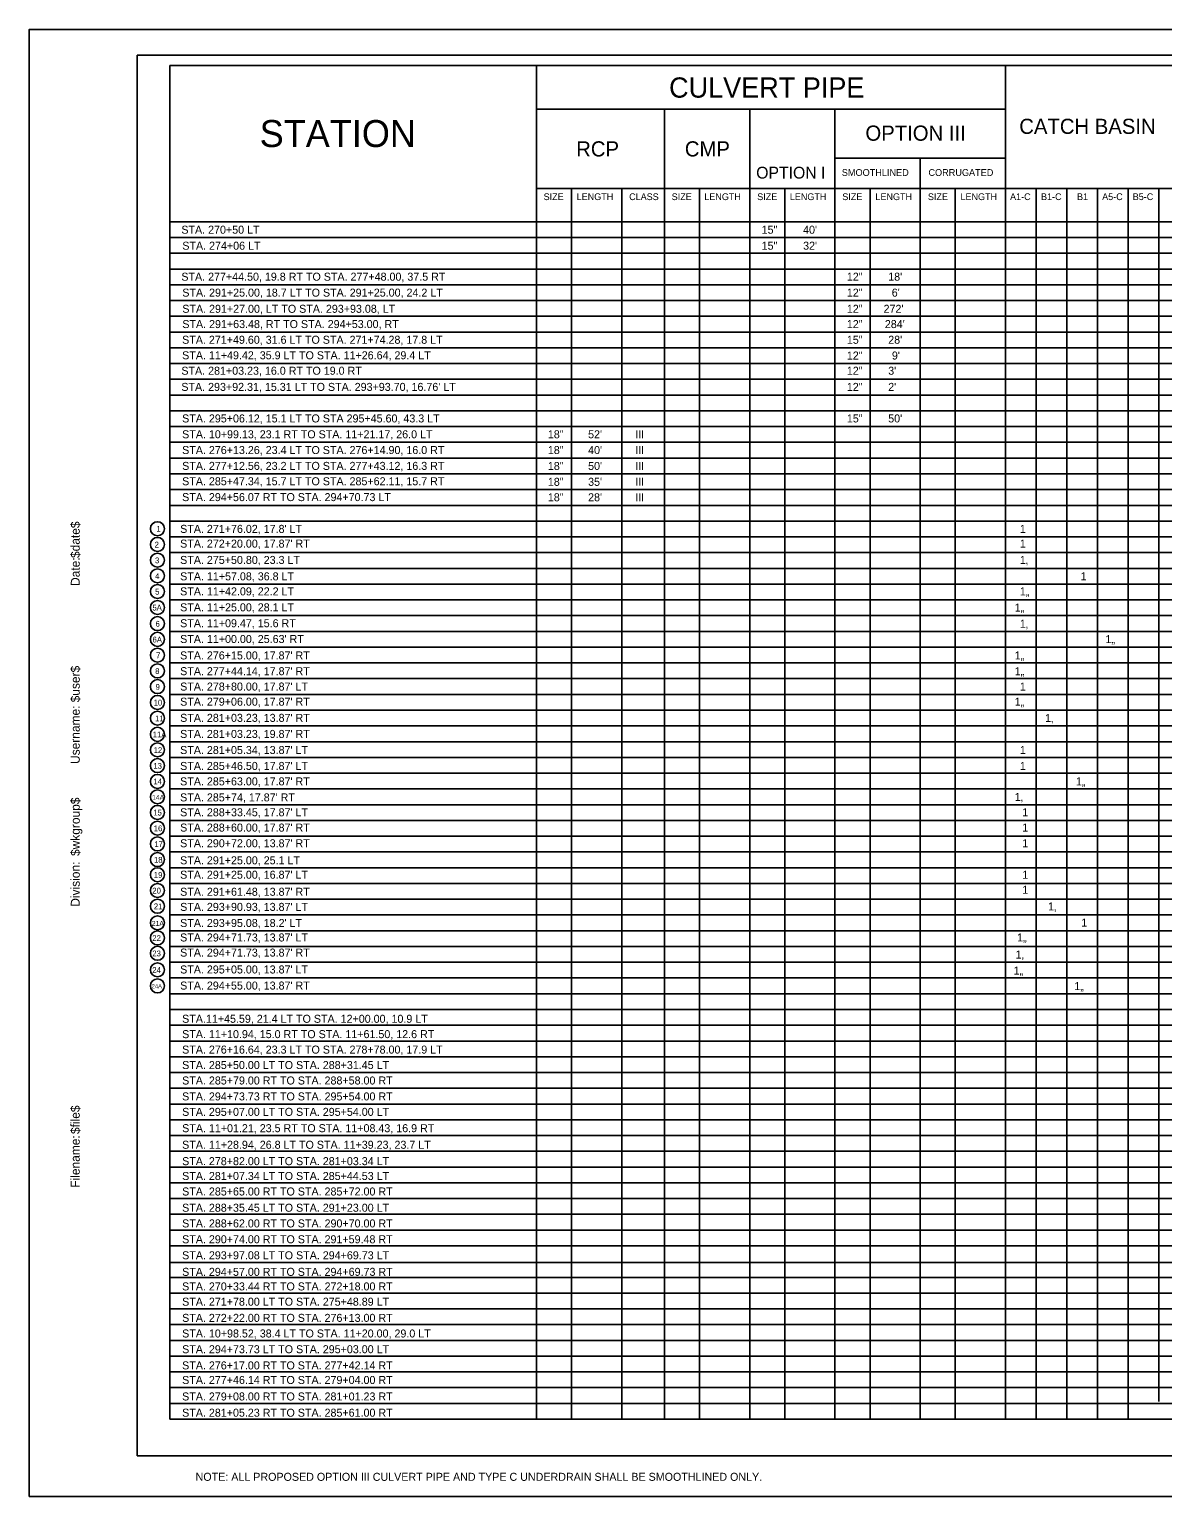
# Model space of a CAD drawing. Extents: x -0.13 to 2.7, y -0.05 to 1.78.
# Drawn here: x -0.135 to 1.282, y -0.051 to 1.782 of the extents above; entities that cross this region are included whole.
import ezdxf

# ---------------------------------------------------------------- set-up
doc = ezdxf.new("R2010")
doc.units = 0
for name, color, linetype in [('ANNOTATION', 7, 'Continuous'), ('BORDER', 7, 'Continuous'), ('PLOT BOUNDARY', 7, 'Continuous')]:
    doc.layers.add(name, color=color, linetype=linetype)

msp = doc.modelspace()

# ---------------------------------------------------------------- linework, layer by layer
at = {"layer": 'ANNOTATION'}
for centre in [(0.0252, 1.1584), (0.0252, 1.1388), (0.0252, 1.1191), (0.0252, 1.0995), (0.0252, 1.08), (0.0252, 1.06), (0.0252, 1.0398), (0.0252, 1.0202), (0.0252, 1.0004), (0.0252, 0.9807), (0.0252, 0.9611), (0.0252, 0.9414), (0.0252, 0.9217), (0.0252, 0.9015), (0.0252, 0.8821), (0.0252, 0.8624), (0.0252, 0.8427), (0.0252, 0.8234), (0.0252, 0.8039), (0.0252, 0.7842), (0.0252, 0.7646), (0.0252, 0.745), (0.0252, 0.7261), (0.0252, 0.7064), (0.0252, 0.6867), (0.0252, 0.666), (0.0252, 0.6471), (0.0252, 0.6279), (0.0252, 0.6073), (0.0252, 0.5872)]:
    msp.add_circle(centre, 0.00875, dxfattribs=at)
at = {"layer": 'BORDER'}
for p, q in [((2.6667, 1.75), (0, 1.75)), ((0, 1.75), (0, 0)), ((0.0408, 1.7373), (2.4546, 1.7373)), ((0.0408, 1.7373), (0.0408, 0.0459)), ((0.4991, 1.6825), (0.4991, 1.7373)), ((1.0852, 1.6825), (1.0852, 1.7373)), ((0.4991, 1.6214), (0.4991, 1.6825)), ((0.4991, 1.6825), (0.5429, 1.6825)), ((0.5429, 1.6825), (0.6056, 1.6825)), ((0.6056, 1.6825), (0.6589, 1.6825)), ((0.6589, 1.6214), (0.6589, 1.6825)), ((0.6589, 1.6825), (0.7028, 1.6825)), ((0.7028, 1.6825), (0.7655, 1.6825)), ((0.7655, 1.6214), (0.7655, 1.6825)), ((0.7655, 1.6825), (0.8093, 1.6825)), ((0.8093, 1.6825), (0.9159, 1.6825)), ((0.872, 1.5836), (0.872, 1.6825)), ((0.9159, 1.6825), (1.0852, 1.6825)), ((1.0852, 1.6214), (1.0852, 1.6825)), ((0.4991, 1.5836), (0.4991, 1.6214)), ((0.6589, 1.5836), (0.6589, 1.6214)), ((0.7655, 1.5836), (0.7655, 1.6214)), ((0.872, 1.6214), (0.9159, 1.6214)), ((0.9159, 1.6214), (1.0224, 1.6214)), ((0.9786, 1.5616), (0.9786, 1.6214)), ((1.0224, 1.6214), (1.0852, 1.6214)), ((1.0852, 1.5836), (1.0852, 1.6214)), ((1.0852, 1.5836), (1.0852, 1.6056)), ((0.4991, 1.5616), (0.4991, 1.5836)), ((0.4991, 1.5836), (0.5429, 1.5836)), ((0.5429, 1.5616), (0.5429, 1.5836)), ((0.5429, 1.5836), (0.6056, 1.5836)), ((0.6056, 1.5616), (0.6056, 1.5836)), ((0.6056, 1.5836), (0.6589, 1.5836)), ((0.6589, 1.5616), (0.6589, 1.5836)), ((0.6589, 1.5836), (0.7028, 1.5836)), ((0.7028, 1.5616), (0.7028, 1.5836)), ((0.7028, 1.5836), (0.7655, 1.5836)), ((0.7655, 1.5616), (0.7655, 1.5836)), ((0.7655, 1.5836), (0.8093, 1.5836)), ((0.8093, 1.5616), (0.8093, 1.5836)), ((0.8093, 1.5836), (0.872, 1.5836)), ((0.872, 1.5616), (0.872, 1.5836)), ((0.872, 1.5836), (0.9159, 1.5836)), ((0.9159, 1.5616), (0.9159, 1.5836)), ((0.9159, 1.5836), (0.9786, 1.5836)), ((0.9786, 1.5836), (1.0224, 1.5836)), ((1.0224, 1.5616), (1.0224, 1.5836)), ((1.0224, 1.5836), (1.0852, 1.5836)), ((1.0852, 1.5616), (1.0852, 1.5836)), ((1.0852, 1.5836), (1.1236, 1.5836)), ((1.1236, 1.5836), (1.1619, 1.5836)), ((1.1236, 1.5836), (1.1236, 0.0459)), ((1.1619, 1.5836), (1.2003, 1.5836)), ((1.1619, 1.5836), (1.1619, 0.0459)), ((1.2003, 1.5836), (1.2386, 1.5836)), ((1.2003, 1.5836), (1.2003, 0.0459)), ((1.2386, 1.5836), (1.277, 1.5836)), ((1.2386, 1.5836), (1.2386, 0.0459)), ((1.2669, 1.5836), (1.3734, 1.5836)), ((1.277, 1.5836), (1.277, 0.0679)), ((0.4991, 1.5616), (0.4991, 0.0459)), ((0.5429, 1.5616), (0.5429, 0.0459)), ((0.6056, 1.5616), (0.6056, 0.0459)), ((0.6589, 1.5616), (0.6589, 0.0459)), ((0.7028, 1.5616), (0.7028, 0.0459)), ((0.7655, 1.5616), (0.7655, 0.0459)), ((0.8093, 1.5616), (0.8093, 0.0459)), ((0.872, 1.5616), (0.872, 0.0459)), ((0.9159, 1.5616), (0.9159, 0.0459)), ((0.9786, 1.5616), (0.9786, 0.0459)), ((1.0224, 1.5616), (1.0224, 0.0459)), ((1.0852, 1.5616), (1.0852, 0.0459)), ((0.0408, 1.5419), (2.4546, 1.5419)), ((0.0408, 1.5223), (2.4546, 1.5223)), ((0.0408, 1.5026), (2.4546, 1.5026)), ((0.0408, 1.4829), (2.4546, 1.4829)), ((0.0408, 1.4632), (2.4546, 1.4632)), ((0.0408, 1.4435), (2.4546, 1.4435)), ((0.0408, 1.4238), (2.4546, 1.4238)), ((0.0408, 1.4041), (2.4546, 1.4041)), ((0.0408, 1.3845), (2.4546, 1.3845)), ((0.0408, 1.3648), (2.4546, 1.3648)), ((0.0408, 1.3451), (2.4546, 1.3451)), ((0.0408, 1.3254), (2.4546, 1.3254)), ((0.0408, 1.3057), (2.4546, 1.3057)), ((0.0408, 1.3057), (2.4546, 1.3057)), ((0.0408, 1.286), (2.4546, 1.286)), ((0.0408, 1.286), (2.4546, 1.286)), ((0.0408, 1.2664), (2.4546, 1.2664)), ((0.0408, 1.2664), (2.4546, 1.2664)), ((0.0408, 1.2467), (2.4546, 1.2467)), ((0.0408, 1.2467), (2.4546, 1.2467)), ((0.0408, 1.227), (2.4546, 1.227)), ((0.0408, 1.2073), (2.4546, 1.2073)), ((0.0408, 1.1876), (2.4546, 1.1876)), ((0.0408, 1.1679), (2.4546, 1.1679)), ((0.0408, 1.1482), (2.4546, 1.1482)), ((0.0408, 1.1286), (2.4546, 1.1286)), ((0.0408, 1.1089), (2.4546, 1.1089)), ((0.0408, 1.0892), (2.4546, 1.0892)), ((0.0408, 1.0695), (2.4546, 1.0695)), ((0.0408, 1.0498), (2.4546, 1.0498)), ((0.0408, 1.0301), (2.4546, 1.0301)), ((0.0408, 1.0104), (2.4546, 1.0104)), ((0.0408, 1.0104), (2.4546, 1.0104)), ((0.0408, 0.9908), (2.4546, 0.9908)), ((0.0408, 0.9711), (2.4546, 0.9711)), ((0.0408, 0.9514), (2.4546, 0.9514)), ((0.0408, 0.9317), (2.4546, 0.9317)), ((0.0408, 0.912), (2.4546, 0.912)), ((0.0408, 0.8923), (2.4546, 0.8923)), ((0.0408, 0.8727), (2.4546, 0.8727)), ((0.0408, 0.853), (2.4546, 0.853)), ((0.0408, 0.8333), (2.4546, 0.8333)), ((0.0408, 0.8136), (2.4546, 0.8136)), ((0.0408, 0.7939), (2.4546, 0.7939)), ((0.0408, 0.7742), (2.4546, 0.7742)), ((0.0408, 0.7545), (2.4546, 0.7545)), ((0.0408, 0.7349), (2.4546, 0.7349)), ((0.0408, 0.7152), (2.4546, 0.7152)), ((0.0408, 0.6955), (2.4546, 0.6955)), ((0.0408, 0.6758), (2.4546, 0.6758)), ((0.0408, 0.6561), (2.4546, 0.6561)), ((0.0408, 0.6364), (2.4546, 0.6364)), ((0.0408, 0.6167), (2.4546, 0.6167)), ((0.0408, 0.5971), (2.4546, 0.5971)), ((0.0408, 0.5774), (2.4546, 0.5774)), ((0.0408, 0.5577), (2.4546, 0.5577)), ((0.0408, 0.538), (2.4546, 0.538)), ((0.0408, 0.5183), (2.4546, 0.5183)), ((0.0408, 0.4986), (2.4546, 0.4986)), ((0.0408, 0.479), (2.4546, 0.479)), ((0.0408, 0.4593), (2.4546, 0.4593)), ((0.0408, 0.4396), (2.4546, 0.4396)), ((0.0408, 0.4199), (2.4546, 0.4199)), ((0.0408, 0.4002), (2.4546, 0.4002)), ((0.0408, 0.3805), (2.4546, 0.3805)), ((0.0408, 0.3608), (2.4546, 0.3608)), ((0.0408, 0.3412), (2.4546, 0.3412)), ((0.0408, 0.3215), (2.4546, 0.3215)), ((0.0408, 0.3018), (2.4546, 0.3018)), ((0.0408, 0.3018), (2.4546, 0.3018)), ((0.0408, 0.2821), (2.4546, 0.2821)), ((0.0408, 0.2624), (2.4546, 0.2624)), ((0.0408, 0.2417), (2.4546, 0.2417)), ((0.0408, 0.223), (2.4546, 0.223)), ((0.0408, 0.2034), (2.4546, 0.2034)), ((0.0408, 0.1837), (2.4546, 0.1837)), ((0.0408, 0.164), (2.4546, 0.164)), ((0.0408, 0.1443), (2.4546, 0.1443)), ((0.0408, 0.1246), (2.4546, 0.1246)), ((0.0408, 0.1049), (2.4546, 0.1049)), ((0.0408, 0.0853), (2.4546, 0.0853)), ((0.0408, 0.0656), (2.4546, 0.0656)), ((0.0408, 0.0459), (2.4546, 0.0459)), ((0, 0), (2.6667, 0))]:
    msp.add_line(p, q, dxfattribs=at)
at = {"layer": 'PLOT BOUNDARY'}
msp.add_lwpolyline([(-0.1349, -0.051), (2.6984, -0.051), (2.6984, 1.7823), (-0.1349, 1.7823)], close=True, dxfattribs=at)

# ---------------------------------------------------------------- texts
at = {"layer": 'ANNOTATION'}
for s, height, p in [('STA. 270+50 LT', 0.01, (0.0551, 1.527)), ('15"', 0.01, (0.7804, 1.527)), ("40'", 0.01, (0.8322, 1.527)), ('STA. 274+06 LT', 0.01, (0.0563, 1.507)), ('15"', 0.01, (0.7804, 1.507)), ("32'", 0.01, (0.8322, 1.507)), ('STA. 277+44.50, 19.8 RT TO STA. 277+48.00, 37.5 RT', 0.01, (0.0551, 1.4683)), ('12"', 0.01, (0.8869, 1.4683)), ("18'", 0.01, (0.9386, 1.4683)), ('STA. 291+25.00, 18.7 LT TO STA. 291+25.00, 24.2 LT', 0.01, (0.0563, 1.4484)), ('12"', 0.01, (0.8869, 1.4484)), ("6'", 0.01, (0.943, 1.4484)), ('STA. 291+27.00, LT TO STA. 293+93.08, LT', 0.01, (0.0563, 1.4282)), ('12"', 0.01, (0.8869, 1.4282)), ("272'", 0.01, (0.9328, 1.4282)), ('STA. 291+63.48, RT TO STA. 294+53.00, RT', 0.01, (0.0563, 1.4091)), ('12"', 0.01, (0.8869, 1.4091)), ("284'", 0.01, (0.9344, 1.4091)), ('STA. 271+49.60, 31.6 LT TO STA. 271+74.28, 17.8 LT', 0.01, (0.0561, 1.3895)), ('15"', 0.01, (0.8869, 1.3895)), ("28'", 0.01, (0.9386, 1.3895)), ('STA. 11+49.42, 35.9 LT TO STA. 11+26.64, 29.4 LT', 0.01, (0.0561, 1.3701)), ('12"', 0.01, (0.8869, 1.3698)), ("9'", 0.01, (0.9432, 1.3698)), ('STA. 281+03.23, 16.0 RT TO 19.0 RT', 0.01, (0.0551, 1.3508)), ('12"', 0.01, (0.8869, 1.3508)), ("3'", 0.01, (0.9386, 1.3508)), ("STA. 293+92.31, 15.31 LT TO STA. 293+93.70, 16.76' LT ", 0.01, (0.0551, 1.3306)), ('12"', 0.01, (0.8869, 1.3306)), ("2'", 0.01, (0.9386, 1.3306)), ('STA. 295+06.12, 15.1 LT TO STA 295+45.60, 43.3 LT', 0.01, (0.0561, 1.2912)), ('15"', 0.01, (0.8869, 1.2912)), ("50'", 0.01, (0.9386, 1.2912)), ('STA. 10+99.13, 23.1 RT TO STA. 11+21.17, 26.0 LT', 0.01, (0.0561, 1.2714)), ('18"', 0.01, (0.5132, 1.2714)), ("52'", 0.01, (0.5635, 1.2714)), ('III', 0.01, (0.6224, 1.2714)), ('STA. 276+13.26, 23.4 LT TO STA. 276+14.90, 16.0 RT', 0.01, (0.0561, 1.2517)), ('18"', 0.01, (0.5132, 1.2517)), ("40'", 0.01, (0.5635, 1.2517)), ('III', 0.01, (0.6224, 1.2517)), ('STA. 277+12.56, 23.2 LT TO STA. 277+43.12, 16.3 RT', 0.01, (0.0561, 1.2319)), ('18"', 0.01, (0.5132, 1.2318)), ("50'", 0.01, (0.5635, 1.2318)), ('III', 0.01, (0.6224, 1.2318)), ('STA. 285+47.34, 15.7 LT TO STA. 285+62.11, 15.7 RT', 0.01, (0.0561, 1.2127)), ('18"', 0.01, (0.5132, 1.212)), ("35'", 0.01, (0.5635, 1.212)), ('III', 0.01, (0.6224, 1.212)), ('STA. 294+56.07 RT TO STA. 294+70.73 LT', 0.01, (0.0561, 1.1929)), ('18"', 0.01, (0.5132, 1.1927)), ("28'", 0.01, (0.5635, 1.1927)), ('III', 0.01, (0.6224, 1.1927)), ('1', 0.00722, (0.024, 1.1546)), ("STA. 271+76.02, 17.8' LT", 0.01, (0.0536, 1.1532)), ('1', 0.01, (1.1031, 1.1532)), ('2', 0.00722, (0.0217, 1.1349)), ("STA. 272+20.00, 17.87' RT", 0.01, (0.0536, 1.1348)), ('1', 0.01, (1.1031, 1.1348)), ('3', 0.00722, (0.0222, 1.1152)), ('STA. 275+50.80, 23.3 LT', 0.01, (0.0536, 1.1144)), ('1‚', 0.01, (1.1031, 1.1144)), ('4', 0.00722, (0.0223, 1.0956)), ('STA. 11+57.08, 36.8 LT', 0.01, (0.0536, 1.0939)), ('1', 0.01, (1.179, 1.0939)), ('5', 0.00722, (0.0223, 1.0761)), ('STA. 11+42.09, 22.2 LT', 0.01, (0.0536, 1.0751)), ('1„', 0.01, (1.1031, 1.0751)), ('5A', 0.00722, (0.0189, 1.0562)), ('STA. 11+25.00, 28.1 LT ', 0.01, (0.0536, 1.0552)), ('1„', 0.01, (1.0967, 1.0549)), ('STA. 11+09.47, 15.6 RT', 0.01, (0.0536, 1.0353)), ('6', 0.00722, (0.0228, 1.036)), ('1‚', 0.01, (1.1031, 1.0347)), ('6A', 0.00722, (0.0191, 1.0163)), ("STA. 11+00.00, 25.63' RT", 0.01, (0.0536, 1.0156)), ('1„', 0.01, (1.2101, 1.0155)), ('7', 0.00722, (0.0235, 0.9966)), ("STA. 276+15.00, 17.87' RT", 0.01, (0.0536, 0.9951)), ('1„', 0.01, (1.0967, 0.9951)), ('8', 0.00722, (0.0224, 0.9769)), ("STA. 277+44.14, 17.87' RT", 0.01, (0.0536, 0.9754)), ('1„', 0.01, (1.0967, 0.9754)), ('9', 0.00722, (0.0229, 0.9572)), ("STA. 278+80.00, 17.87' LT", 0.01, (0.0536, 0.9562)), ('1', 0.01, (1.1031, 0.9562)), ('10', 0.00722, (0.0204, 0.9375)), ("STA. 279+06.00, 17.87' RT", 0.01, (0.0536, 0.9373)), ('1„', 0.01, (1.0967, 0.9373)), ('11', 0.00722, (0.0224, 0.9178)), ("STA. 281+03.23, 13.87' RT", 0.01, (0.0536, 0.9171)), ('1‚', 0.01, (1.1347, 0.9169)), ('11A', 0.00722, (0.0193, 0.8976)), ("STA. 281+03.23, 19.87' RT", 0.01, (0.0536, 0.897)), ('12', 0.00722, (0.0204, 0.8782)), ("STA. 281+05.34, 13.87' LT", 0.01, (0.0536, 0.8769)), ('1', 0.01, (1.1031, 0.8769)), ('13', 0.00722, (0.0201, 0.8585)), ("STA. 285+46.50, 17.87' LT", 0.01, (0.0536, 0.857)), ('1', 0.01, (1.1031, 0.857)), ('14', 0.00722, (0.0201, 0.8389)), ("STA. 285+63.00, 17.87' RT", 0.01, (0.0536, 0.8377)), ('1„', 0.01, (1.1732, 0.8377)), ('14A', 0.00614, (0.0186, 0.8197)), ("STA. 285+74, 17.87' RT", 0.01, (0.0536, 0.8177)), ('1‚', 0.01, (1.0968, 0.8184)), ('15', 0.00722, (0.02, 0.8001)), ("STA. 288+33.45, 17.87' LT", 0.01, (0.0536, 0.7991)), ('1', 0.01, (1.1061, 0.7991)), ("STA. 288+60.00, 17.87' RT", 0.01, (0.0536, 0.78)), ('1', 0.01, (1.1061, 0.78)), ('16', 0.00722, (0.0206, 0.7804)), ("STA. 290+72.00, 13.87' RT", 0.01, (0.0536, 0.7604)), ('1', 0.01, (1.1061, 0.7604)), ('17', 0.00722, (0.0213, 0.7607)), ('18', 0.00722, (0.0209, 0.7411)), ('STA. 291+25.00, 25.1 LT', 0.01, (0.0536, 0.7391)), ('19', 0.00722, (0.0207, 0.7223)), ("STA. 291+25.00, 16.87' LT", 0.01, (0.0536, 0.7211)), ('1', 0.01, (1.1061, 0.7211)), ('20', 0.00722, (0.0188, 0.7026)), ("STA. 291+61.48, 13.87' RT", 0.01, (0.0536, 0.6998)), ('1', 0.01, (1.1061, 0.7023)), ('21', 0.00722, (0.0207, 0.6829)), ("STA. 293+90.93, 13.87' LT", 0.01, (0.0536, 0.6809)), ('1‚', 0.01, (1.1384, 0.6815)), ('21A', 0.00614, (0.0182, 0.6622)), ("STA. 293+95.08, 18.2' LT", 0.01, (0.0536, 0.6608)), ('1', 0.01, (1.1799, 0.6612)), ('22', 0.00722, (0.0188, 0.6433)), ("STA. 294+71.73, 13.87' LT", 0.01, (0.0536, 0.6427)), ('1„', 0.01, (1.0997, 0.6427)), ('23', 0.00722, (0.0188, 0.6241)), ("STA. 294+71.73, 13.87' RT", 0.01, (0.0536, 0.6238)), ('1‚', 0.01, (1.0978, 0.6214)), ('24', 0.00722, (0.0188, 0.6034)), ("STA. 295+05.00, 13.87' LT", 0.01, (0.0536, 0.6027)), ('1„', 0.01, (1.0953, 0.6013)), ('24A', 0.00522, (0.018, 0.5841)), ("STA. 294+55.00, 13.87' RT", 0.01, (0.0536, 0.5826)), ('1„', 0.01, (1.1712, 0.5819)), ('STA.11+45.59, 21.4 LT TO STA. 12+00.00, 10.9 LT', 0.01, (0.0561, 0.5411)), ('STA. 11+10.94, 15.0 RT TO STA. 11+61.50, 12.6 RT', 0.01, (0.0561, 0.5219)), ('STA. 276+16.64, 23.3 LT TO STA. 278+78.00, 17.9 LT', 0.01, (0.0561, 0.5026)), ('STA. 285+50.00 LT TO STA. 288+31.45 LT', 0.01, (0.0561, 0.4833)), ('STA. 285+79.00 RT TO STA. 288+58.00 RT', 0.01, (0.0561, 0.464)), ('STA. 294+73.73 RT TO STA. 295+54.00 RT', 0.01, (0.0561, 0.4441)), ('STA. 295+07.00 LT TO STA. 295+54.00 LT', 0.01, (0.0561, 0.4248)), ('STA. 11+01.21, 23.5 RT TO STA. 11+08.43, 16.9 RT', 0.01, (0.0561, 0.4044)), ('STA. 11+28.94, 26.8 LT TO STA. 11+39.23, 23.7 LT', 0.01, (0.0561, 0.3837)), ('STA. 278+82.00 LT TO STA. 281+03.34 LT', 0.01, (0.0561, 0.3632)), ('STA. 281+07.34 LT TO STA. 285+44.53 LT', 0.01, (0.0561, 0.3447)), ('STA. 285+65.00 RT TO STA. 285+72.00 RT', 0.01, (0.0561, 0.3253)), ('STA. 288+35.45 LT TO STA. 291+23.00 LT', 0.01, (0.0561, 0.305)), ('STA. 288+62.00 RT TO STA. 290+70.00 RT', 0.01, (0.0561, 0.2854)), ('STA. 290+74.00 RT TO STA. 291+59.48 RT', 0.01, (0.0561, 0.2656)), ('STA. 293+97.08 LT TO STA. 294+69.73 LT', 0.01, (0.0561, 0.2456)), ('STA. 294+57.00 RT TO STA. 294+69.73 RT', 0.01, (0.0561, 0.2249)), ('STA. 270+33.44 RT TO STA. 272+18.00 RT', 0.01, (0.0561, 0.2067)), ('STA. 271+78.00 LT TO STA. 275+48.89 LT', 0.01, (0.0561, 0.1876)), ('STA. 272+22.00 RT TO STA. 276+13.00 RT', 0.01, (0.0561, 0.1674)), ('STA. 10+98.52, 38.4 LT TO STA. 11+20.00, 29.0 LT', 0.01, (0.0561, 0.1479)), ('STA. 294+73.73 LT TO STA. 295+03.00 LT', 0.01, (0.0561, 0.1282)), ('STA. 276+17.00 RT TO STA. 277+42.14 RT', 0.01, (0.0561, 0.108)), ('STA. 277+46.14 RT TO STA. 279+04.00 RT', 0.01, (0.0561, 0.0898)), ('STA. 279+08.00 RT TO STA. 281+01.23 RT', 0.01, (0.0561, 0.0692)), ('STA. 281+05.23 RT TO STA. 285+61.00 RT', 0.01, (0.0561, 0.0489)), ('NOTE: ALL PROPOSED OPTION III CULVERT PIPE AND TYPE C UNDERDRAIN SHALL BE SMOOTHLINED ONLY.', 0.01, (0.0729, -0.0312))]:
    msp.add_text(s, height=height, dxfattribs=at).set_placement(p)
at = {"layer": 'BORDER'}
for s, height, p in [('CULVERT PIPE', 0.025276, (0.6647, 1.697)), ('STATION', 0.0337, (0.153, 1.6353)), ('CATCH BASIN', 0.018957, (1.1024, 1.6517)), ('OPTION III', 0.01896, (0.9101, 1.6432)), ('RCP', 0.01896, (0.5486, 1.6235)), ('CMP', 0.01896, (0.6844, 1.6235)), ('OPTION I', 0.01474, (0.7736, 1.5959)), ('SMOOTHLINED', 0.008531, (0.8806, 1.5992)), ('CORRUGATED', 0.00853, (0.9889, 1.5992)), ('SIZE', 0.00843, (0.5079, 1.569)), ('LENGTH', 0.00843, (0.5492, 1.569)), ('CLASS', 0.00843, (0.6148, 1.569)), ('SIZE', 0.00843, (0.668, 1.569)), ('LENGTH', 0.00843, (0.7087, 1.569)), ('SIZE', 0.00843, (0.7749, 1.569)), ('LENGTH', 0.00843, (0.8156, 1.569)), ('SIZE', 0.00843, (0.8812, 1.569)), ('LENGTH', 0.00843, (0.9226, 1.569)), ('SIZE', 0.00843, (0.9882, 1.569)), ('LENGTH', 0.00843, (1.0289, 1.569)), ('A1-C', 0.00843, (1.0909, 1.569)), ('B1-C', 0.00843, (1.1296, 1.569)), ('B1', 0.00843, (1.1746, 1.569)), ('A5-C', 0.00843, (1.206, 1.569)), ('B5-C', 0.00843, (1.2442, 1.569))]:
    msp.add_text(s, height=height, dxfattribs=at).set_placement(p)
for s, p in [('$date$', (-0.0719, 1.1218)), ('Date:', (-0.0719, 1.0869)), ('$user$', (-0.0719, 0.9415)), ('Username:', (-0.0719, 0.8645)), ('$wkgroup$', (-0.0719, 0.7495)), ('Division:', (-0.0719, 0.6861)), ('$file$', (-0.0719, 0.4021)), ('Filename:', (-0.0719, 0.335))]:
    msp.add_text(s, height=0.01116, rotation=90, dxfattribs=at).set_placement(p)

doc.saveas('drawing.dxf')
